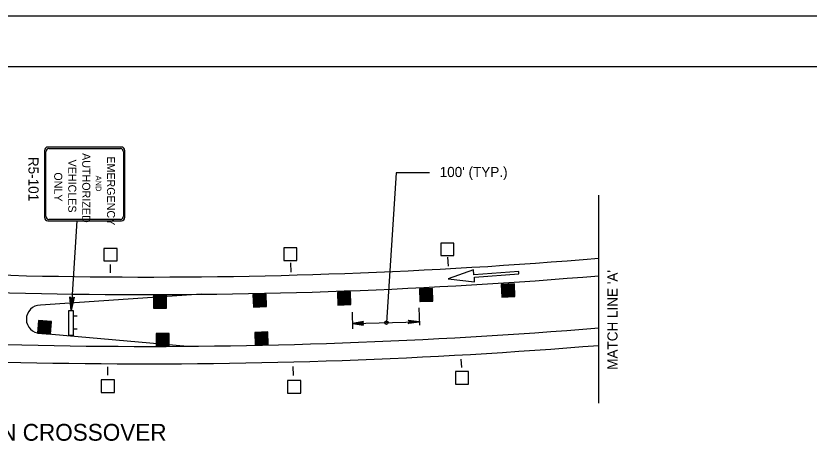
# Model space of a CAD drawing. Extents: x 640253 to 641999, y 298458 to 299646.
# Drawn here: x 641285.7 to 641521.2, y 299517.6 to 299645.6 of the extents above; entities that cross this region are included whole.
import ezdxf

# ---------------------------------------------------------------- set-up
doc = ezdxf.new("R2010")
doc.units = 0
for name, color, linetype in [('1', 7, 'Continuous'), ('2', 7, 'Continuous'), ('PLT-BNDY', 7, 'Continuous')]:
    doc.layers.add(name, color=color, linetype=linetype)

msp = doc.modelspace()

# ---------------------------------------------------------------- linework, layer by layer
at = {"layer": '1'}
msp.add_line((641134.31, 299630.63), (641920.31, 299630.63), dxfattribs=at)
at = {"layer": '2'}
for p, q in [((641317.01, 299606.68), (641295.14, 299606.68)), ((641295.42, 299606.27), (641316.73, 299606.27)), ((641294.19, 299605.58), (641294.19, 299585.83)), ((641294.54, 299586.15), (641294.54, 299605.26)), ((641317.61, 299605.26), (641317.61, 299586.15)), ((641317.96, 299585.83), (641317.96, 299605.58)), ((641458.78, 299530.67), (641458.78, 299592.35)), ((641295.14, 299584.73), (641317.01, 299584.73)), ((641316.73, 299585.14), (641295.42, 299585.14)), ((641414.07, 299571.28), (641413.91, 299574.01)), ((641313.76, 299569.29), (641313.78, 299571.77)), ((641367.39, 299569.57), (641367.33, 299572.3)), ((641421.56, 299570.22), (641414, 299567.58)), ((641421.66, 299568.78), (641421.56, 299570.22)), ((641434.95, 299569.7), (641421.66, 299568.78)), ((641421.79, 299568.08), (641435, 299568.99)), ((641421.88, 299566.64), (641421.79, 299568.08)), ((641435, 299568.99), (641434.95, 299569.7)), ((641414, 299567.58), (641421.88, 299566.64)), ((641292.94, 299559.81), (641337.84, 299562.94)), ((641339.24, 299562.96), (641340.74, 299563.06)), ((641405.33, 299558.94), (641405.46, 299553.77)), ((641302.59, 299556.51), (641303.84, 299556.51)), ((641385.52, 299557.67), (641385.64, 299552.69)), ((641385.6, 299554.3), (641405.43, 299554.77)), ((641302.59, 299552.66), (641303.84, 299552.66)), ((641292.94, 299551.4), (641336.58, 299547.52)), ((641418.05, 299541.21), (641417.9, 299543.69)), ((641312.92, 299538.92), (641312.94, 299541.4)), ((641368.05, 299538.84), (641367.99, 299541.56))]:
    msp.add_line(p, q, dxfattribs=at)
for points in [[(641408.49, 299598.98), (641398.57, 299598.98), (641395.68, 299554.54)], [(641303.8, 299584.73), (641302.04, 299558.18)], [(641429.91, 299562.14), (641433.81, 299562.28), (641433.68, 299566.02), (641429.78, 299565.88), (641429.91, 299562.14), (641433.62, 299565.95), (641429.85, 299565.82), (641429.98, 299562.19), (641433.74, 299562.32), (641433.62, 299565.88), (641429.93, 299565.75), (641430.05, 299562.26), (641433.66, 299562.39), (641433.53, 299565.79), (641430, 299565.66), (641430.12, 299562.32), (641433.59, 299562.45), (641433.48, 299565.73), (641430.07, 299565.61), (641430.18, 299562.39), (641433.51, 299562.51), (641433.39, 299565.66), (641430.14, 299565.54), (641430.24, 299562.45), (641433.44, 299562.58), (641433.32, 299565.58), (641430.21, 299565.47), (641430.31, 299562.52), (641433.37, 299562.64), (641433.25, 299565.51), (641430.28, 299565.4), (641430.36, 299562.6), (641433.28, 299562.72), (641433.19, 299565.42), (641430.37, 299565.33), (641430.43, 299562.65), (641433.18, 299562.79), (641433.1, 299565.35), (641430.45, 299565.26), (641430.5, 299562.72), (641433.1, 299562.85), (641433.02, 299565.29), (641430.53, 299565.19), (641430.58, 299562.76), (641433.01, 299562.91), (641432.92, 299565.21), (641430.63, 299565.1), (641430.61, 299564), (641430.65, 299562.83), (641432.93, 299562.99), (641432.83, 299565.11), (641430.71, 299565), (641430.74, 299562.91), (641432.84, 299563.05), (641432.74, 299565.03), (641430.82, 299564.9), (641430.84, 299563), (641432.71, 299563.12), (641432.63, 299564.9), (641430.96, 299564.8), (641430.96, 299563.14), (641432.56, 299563.22), (641432.49, 299564.79), (641431.12, 299564.68), (641431.09, 299563.26), (641431.1, 299563.26), (641432.41, 299563.35), (641432.36, 299564.64), (641431.26, 299564.56), (641431.23, 299563.39), (641432.25, 299563.49), (641432.22, 299564.48), (641431.4, 299564.43), (641431.39, 299563.55), (641432.09, 299563.6), (641432.04, 299564.34), (641431.57, 299564.3), (641431.57, 299563.69), (641431.91, 299563.74), (641431.9, 299564.18), (641431.75, 299564.21), (641431.74, 299563.85)], [(641381.24, 299559.77), (641385.14, 299559.9), (641385.01, 299563.65), (641381.11, 299563.51), (641381.24, 299559.77), (641384.95, 299563.57), (641381.18, 299563.44), (641381.3, 299559.82), (641385.07, 299559.95), (641384.95, 299563.51), (641381.26, 299563.38), (641381.38, 299559.89), (641384.99, 299560.02), (641384.86, 299563.42), (641381.33, 299563.29), (641381.45, 299559.95), (641384.92, 299560.07), (641384.81, 299563.36), (641381.4, 299563.24), (641381.51, 299560.01), (641384.84, 299560.14), (641384.72, 299563.28), (641381.47, 299563.17), (641381.57, 299560.07), (641384.77, 299560.2), (641384.65, 299563.21), (641381.54, 299563.1), (641381.63, 299560.14), (641384.7, 299560.27), (641384.58, 299563.14), (641381.61, 299563.03), (641381.69, 299560.22), (641384.61, 299560.35), (641384.52, 299563.04), (641381.7, 299562.96), (641381.76, 299560.27), (641384.51, 299560.42), (641384.43, 299562.98), (641381.78, 299562.89), (641381.83, 299560.34), (641384.43, 299560.48), (641384.34, 299562.92), (641381.86, 299562.81), (641381.91, 299560.39), (641384.34, 299560.54), (641384.25, 299562.84), (641381.96, 299562.73), (641381.94, 299561.63), (641381.98, 299560.46), (641384.26, 299560.61), (641384.16, 299562.74), (641382.03, 299562.62), (641382.07, 299560.54), (641384.17, 299560.68), (641384.07, 299562.66), (641382.15, 299562.53), (641382.17, 299560.63), (641384.04, 299560.74), (641383.96, 299562.52), (641382.28, 299562.43), (641382.28, 299560.76), (641383.89, 299560.85), (641383.82, 299562.41), (641382.45, 299562.31), (641382.42, 299560.88), (641382.43, 299560.88), (641383.74, 299560.98), (641383.68, 299562.26), (641382.58, 299562.19), (641382.56, 299561.01), (641383.58, 299561.11), (641383.55, 299562.1), (641382.73, 299562.06), (641382.72, 299561.17), (641383.42, 299561.23), (641383.36, 299561.97), (641382.9, 299561.92), (641382.9, 299561.32), (641383.24, 299561.36), (641383.23, 299561.81), (641383.08, 299561.83), (641383.07, 299561.47)], [(641405.61, 299560.8), (641409.51, 299560.94), (641409.38, 299564.69), (641405.48, 299564.55), (641405.61, 299560.8), (641409.32, 299564.61), (641405.55, 299564.48), (641405.68, 299560.86), (641409.45, 299560.99), (641409.32, 299564.55), (641405.63, 299564.42), (641405.75, 299560.93), (641409.36, 299561.05), (641409.24, 299564.45), (641405.7, 299564.33), (641405.82, 299560.99), (641409.29, 299561.11), (641409.18, 299564.39), (641405.77, 299564.27), (641405.88, 299561.05), (641409.22, 299561.17), (641409.09, 299564.32), (641405.84, 299564.21), (641405.94, 299561.11), (641409.14, 299561.24), (641409.02, 299564.25), (641405.91, 299564.14), (641406.01, 299561.18), (641409.07, 299561.31), (641408.96, 299564.17), (641405.98, 299564.07), (641406.06, 299561.26), (641408.98, 299561.38), (641408.89, 299564.08), (641406.07, 299563.99), (641406.13, 299561.31), (641408.88, 299561.46), (641408.8, 299564.02), (641406.15, 299563.93), (641406.2, 299561.38), (641408.8, 299561.51), (641408.72, 299563.96), (641406.23, 299563.85), (641406.28, 299561.42), (641408.71, 299561.58), (641408.62, 299563.88), (641406.33, 299563.77), (641406.31, 299562.67), (641406.36, 299561.5), (641408.63, 299561.65), (641408.53, 299563.78), (641406.41, 299563.66), (641406.44, 299561.58), (641408.54, 299561.72), (641408.44, 299563.7), (641406.51, 299563.57), (641406.55, 299561.67), (641408.41, 299561.78), (641408.33, 299563.56), (641406.66, 299563.47), (641406.66, 299561.8), (641408.26, 299561.88), (641408.19, 299563.45), (641406.82, 299563.35), (641406.79, 299561.92), (641406.8, 299561.92), (641408.11, 299562.02), (641408.06, 299563.3), (641406.96, 299563.22), (641406.93, 299562.05), (641407.95, 299562.15), (641407.93, 299563.14), (641407.1, 299563.09), (641407.09, 299562.21), (641407.79, 299562.27), (641407.74, 299563.01), (641407.27, 299562.96), (641407.27, 299562.36), (641407.61, 299562.4), (641407.59, 299562.85), (641407.45, 299562.87), (641407.44, 299562.51)], [(641302.76, 299561.93), (641302.47, 299561.81), (641302.04, 299558.18), (641302.76, 299561.93), (641302.93, 299562.1), (641302.04, 299558.18), (641302.1, 299561.83), (641301.83, 299561.97), (641302.04, 299558.18), (641301.66, 299562.2), (641301.83, 299561.97)], [(641326.48, 299558.84), (641330.38, 299558.84), (641330.38, 299562.59), (641326.48, 299562.59), (641326.48, 299558.84), (641330.32, 299562.52), (641326.55, 299562.52), (641326.55, 299558.89), (641330.32, 299558.89), (641330.32, 299562.45), (641326.62, 299562.45), (641326.62, 299558.96), (641330.24, 299558.96), (641330.23, 299562.36), (641326.69, 299562.36), (641326.69, 299559.02), (641330.17, 299559.02), (641330.17, 299562.3), (641326.76, 299562.3), (641326.76, 299559.08), (641330.09, 299559.09), (641330.08, 299562.24), (641326.83, 299562.24), (641326.82, 299559.14), (641330.03, 299559.16), (641330.01, 299562.16), (641326.9, 299562.16), (641326.89, 299559.2), (641329.96, 299559.22), (641329.94, 299562.09), (641326.96, 299562.09), (641326.95, 299559.28), (641329.87, 299559.3), (641329.87, 299562), (641327.05, 299562.01), (641327.01, 299559.33), (641329.77, 299559.38), (641329.78, 299561.94), (641327.13, 299561.94), (641327.09, 299559.4), (641329.69, 299559.44), (641329.69, 299561.89), (641327.21, 299561.87), (641327.17, 299559.44), (641329.6, 299559.51), (641329.6, 299561.81), (641327.3, 299561.78), (641327.25, 299560.68), (641327.25, 299559.51), (641329.53, 299559.59), (641329.5, 299561.71), (641327.37, 299561.67), (641327.33, 299559.59), (641329.44, 299559.65), (641329.41, 299561.63), (641327.48, 299561.57), (641327.44, 299559.67), (641329.31, 299559.72), (641329.3, 299561.5), (641327.62, 299561.47), (641327.56, 299559.8), (641329.17, 299559.83), (641329.15, 299561.4), (641327.77, 299561.34), (641327.7, 299559.91), (641327.71, 299559.91), (641329.02, 299559.97), (641329.01, 299561.25), (641327.91, 299561.21), (641327.84, 299560.05), (641328.86, 299560.1), (641328.87, 299561.1), (641328.05, 299561.08), (641328.01, 299560.2), (641328.71, 299560.23), (641328.68, 299560.97), (641328.21, 299560.94), (641328.19, 299560.34), (641328.53, 299560.37), (641328.53, 299560.81), (641328.39, 299560.84), (641328.37, 299560.48)], [(641356.19, 299559.16), (641360.08, 299559.3), (641359.96, 299563.04), (641356.06, 299562.9), (641356.19, 299559.16), (641359.9, 299562.97), (641356.13, 299562.84), (641356.25, 299559.21), (641360.02, 299559.34), (641359.9, 299562.9), (641356.21, 299562.77), (641356.33, 299559.28), (641359.94, 299559.41), (641359.81, 299562.81), (641356.28, 299562.68), (641356.39, 299559.34), (641359.87, 299559.47), (641359.76, 299562.75), (641356.35, 299562.63), (641356.46, 299559.41), (641359.79, 299559.53), (641359.67, 299562.68), (641356.42, 299562.56), (641356.52, 299559.47), (641359.72, 299559.6), (641359.59, 299562.6), (641356.49, 299562.49), (641356.58, 299559.54), (641359.65, 299559.66), (641359.53, 299562.53), (641356.56, 299562.42), (641356.64, 299559.62), (641359.56, 299559.74), (641359.47, 299562.44), (641356.65, 299562.35), (641356.71, 299559.67), (641359.46, 299559.81), (641359.38, 299562.37), (641356.73, 299562.28), (641356.78, 299559.74), (641359.38, 299559.87), (641359.29, 299562.31), (641356.81, 299562.21), (641356.86, 299559.78), (641359.29, 299559.93), (641359.2, 299562.23), (641356.9, 299562.12), (641356.89, 299561.02), (641356.93, 299559.85), (641359.21, 299560.01), (641359.11, 299562.13), (641356.98, 299562.02), (641357.02, 299559.93), (641359.12, 299560.07), (641359.02, 299562.05), (641357.09, 299561.92), (641357.12, 299560.02), (641358.99, 299560.14), (641358.91, 299561.92), (641357.23, 299561.82), (641357.23, 299560.15), (641358.84, 299560.24), (641358.77, 299561.81), (641357.39, 299561.7), (641357.37, 299560.27), (641357.38, 299560.27), (641358.69, 299560.37), (641358.63, 299561.66), (641357.53, 299561.58), (641357.51, 299560.41), (641358.53, 299560.5), (641358.5, 299561.49), (641357.68, 299561.45), (641357.67, 299560.57), (641358.37, 299560.62), (641358.31, 299561.36), (641357.85, 299561.32), (641357.85, 299560.71), (641358.19, 299560.75), (641358.17, 299561.2), (641358.03, 299561.22), (641358.02, 299560.86)], [(641292.09, 299551.42), (641295.98, 299551.15), (641296.24, 299554.89), (641292.35, 299555.16), (641292.09, 299551.42), (641296.17, 299554.82), (641292.41, 299555.09), (641292.16, 299551.47), (641295.92, 299551.21), (641296.16, 299554.76), (641292.48, 299555.01), (641292.24, 299551.53), (641295.84, 299551.28), (641296.07, 299554.67), (641292.54, 299554.92), (641292.31, 299551.59), (641295.78, 299551.35), (641296.01, 299554.62), (641292.61, 299554.86), (641292.38, 299551.64), (641295.71, 299551.42), (641295.92, 299554.56), (641292.67, 299554.79), (641292.45, 299551.7), (641295.64, 299551.49), (641295.83, 299554.49), (641292.73, 299554.71), (641292.52, 299551.76), (641295.58, 299551.56), (641295.76, 299554.42), (641292.8, 299554.63), (641292.58, 299551.83), (641295.5, 299551.65), (641295.69, 299554.34), (641292.88, 299554.55), (641292.65, 299551.87), (641295.41, 299551.73), (641295.59, 299554.29), (641292.95, 299554.47), (641292.73, 299551.94), (641295.33, 299551.79), (641295.5, 299554.24), (641293.02, 299554.39), (641292.82, 299551.97), (641295.25, 299551.87), (641295.4, 299554.16), (641293.11, 299554.29), (641292.98, 299553.2), (641292.9, 299552.03), (641295.18, 299551.95), (641295.3, 299554.07), (641293.17, 299554.19), (641292.99, 299552.11), (641295.09, 299552.02), (641295.2, 299554), (641293.27, 299554.08), (641293.1, 299552.19), (641294.97, 299552.1), (641295.08, 299553.89), (641293.4, 299553.96), (641293.23, 299552.3), (641294.83, 299552.22), (641294.92, 299553.79), (641293.55, 299553.82), (641293.37, 299552.41), (641293.38, 299552.41), (641294.7, 299552.37), (641294.78, 299553.65), (641293.68, 299553.69), (641293.53, 299552.53), (641294.55, 299552.51), (641294.63, 299553.51), (641293.81, 299553.55), (641293.7, 299552.67), (641294.4, 299552.65), (641294.43, 299553.39), (641293.96, 299553.4), (641293.9, 299552.79), (641294.24, 299552.8), (641294.27, 299553.25), (641294.13, 299553.29), (641294.08, 299552.93)], [(641388.76, 299554.7), (641388.64, 299554.47), (641385.6, 299554.3), (641388.76, 299554.7), (641388.91, 299554.84), (641385.6, 299554.3), (641388.64, 299554.14), (641388.74, 299553.92), (641385.6, 299554.3), (641388.91, 299553.78), (641388.74, 299553.92)], [(641402.27, 299555.17), (641402.4, 299554.94), (641405.43, 299554.77), (641402.27, 299555.17), (641402.12, 299555.31), (641405.43, 299554.77), (641402.4, 299554.61), (641402.29, 299554.39), (641405.43, 299554.77), (641402.12, 299554.25), (641402.29, 299554.39)], [(641356.71, 299547.91), (641360.61, 299548.05), (641360.48, 299551.79), (641356.58, 299551.65), (641356.71, 299547.91), (641360.42, 299551.72), (641356.65, 299551.59), (641356.78, 299547.96), (641360.55, 299548.1), (641360.42, 299551.65), (641356.73, 299551.52), (641356.85, 299548.04), (641360.46, 299548.16), (641360.34, 299551.56), (641356.8, 299551.44), (641356.92, 299548.1), (641360.39, 299548.21), (641360.28, 299551.5), (641356.87, 299551.38), (641356.98, 299548.16), (641360.32, 299548.28), (641360.19, 299551.43), (641356.94, 299551.31), (641357.04, 299548.21), (641360.24, 299548.35), (641360.12, 299551.35), (641357.01, 299551.24), (641357.11, 299548.29), (641360.17, 299548.41), (641360.06, 299551.28), (641357.08, 299551.17), (641357.16, 299548.37), (641360.08, 299548.49), (641359.99, 299551.19), (641357.17, 299551.1), (641357.23, 299548.42), (641359.98, 299548.56), (641359.9, 299551.12), (641357.25, 299551.03), (641357.3, 299548.49), (641359.9, 299548.62), (641359.82, 299551.06), (641357.33, 299550.96), (641357.38, 299548.53), (641359.81, 299548.68), (641359.72, 299550.98), (641357.43, 299550.87), (641357.41, 299549.77), (641357.46, 299548.6), (641359.73, 299548.76), (641359.63, 299550.88), (641357.51, 299550.77), (641357.54, 299548.68), (641359.64, 299548.82), (641359.55, 299550.8), (641357.62, 299550.67), (641357.65, 299548.77), (641359.51, 299548.89), (641359.43, 299550.67), (641357.76, 299550.57), (641357.76, 299548.9), (641359.36, 299548.99), (641359.29, 299550.56), (641357.92, 299550.45), (641357.89, 299549.02), (641357.9, 299549.02), (641359.21, 299549.12), (641359.16, 299550.41), (641358.06, 299550.33), (641358.03, 299549.16), (641359.05, 299549.25), (641359.03, 299550.25), (641358.2, 299550.2), (641358.19, 299549.32), (641358.89, 299549.37), (641358.84, 299550.11), (641358.37, 299550.07), (641358.37, 299549.46), (641358.71, 299549.5), (641358.7, 299549.95), (641358.55, 299549.97), (641358.54, 299549.61)], [(641327.29, 299547.54), (641331.19, 299547.54), (641331.19, 299551.29), (641327.29, 299551.29), (641327.29, 299547.54), (641331.13, 299551.21), (641327.36, 299551.21), (641327.36, 299547.59), (641331.13, 299547.59), (641331.13, 299551.15), (641327.43, 299551.15), (641327.43, 299547.66), (641331.05, 299547.66), (641331.04, 299551.06), (641327.5, 299551.06), (641327.5, 299547.72), (641330.98, 299547.72), (641330.98, 299551), (641327.57, 299551), (641327.57, 299547.77), (641330.91, 299547.79), (641330.9, 299550.93), (641327.64, 299550.93), (641327.63, 299547.84), (641330.84, 299547.85), (641330.82, 299550.86), (641327.71, 299550.86), (641327.7, 299547.9), (641330.77, 299547.92), (641330.75, 299550.79), (641327.78, 299550.79), (641327.76, 299547.98), (641330.68, 299548), (641330.68, 299550.7), (641327.86, 299550.71), (641327.82, 299548.03), (641330.58, 299548.08), (641330.59, 299550.64), (641327.94, 299550.64), (641327.9, 299548.1), (641330.51, 299548.14), (641330.51, 299550.58), (641328.02, 299550.56), (641327.98, 299548.14), (641330.42, 299548.2), (641330.41, 299550.51), (641328.11, 299550.47), (641328.06, 299549.37), (641328.06, 299548.2), (641330.34, 299548.28), (641330.31, 299550.41), (641328.19, 299550.37), (641328.15, 299548.28), (641330.25, 299548.35), (641330.22, 299550.33), (641328.29, 299550.27), (641328.26, 299548.37), (641330.12, 299548.42), (641330.11, 299550.2), (641328.43, 299550.16), (641328.37, 299548.5), (641329.98, 299548.52), (641329.96, 299550.1), (641328.58, 299550.04), (641328.51, 299548.61), (641328.52, 299548.61), (641329.83, 299548.66), (641329.82, 299549.95), (641328.72, 299549.91), (641328.65, 299548.74), (641329.68, 299548.8), (641329.68, 299549.79), (641328.86, 299549.77), (641328.82, 299548.9), (641329.52, 299548.92), (641329.49, 299549.67), (641329.03, 299549.64), (641329.01, 299549.03), (641329.34, 299549.06), (641329.34, 299549.51), (641329.2, 299549.54), (641329.18, 299549.18)]]:
    msp.add_lwpolyline(points, dxfattribs=at)
for points in [[(641411.83, 299574.43), (641415.72, 299574.43), (641415.72, 299578.17), (641411.83, 299578.17)], [(641311.81, 299572.84), (641315.7, 299572.84), (641315.7, 299576.58), (641311.81, 299576.58)], [(641365.22, 299572.95), (641369.11, 299572.95), (641369.11, 299576.7), (641365.22, 299576.7)], [(641301.37, 299550.68), (641301.37, 299558.18), (641302.62, 299558.18), (641302.62, 299550.68)], [(641416.2, 299536.29), (641420.1, 299536.29), (641420.1, 299540.04), (641416.2, 299540.04)], [(641311.01, 299533.83), (641314.9, 299533.83), (641314.9, 299537.58), (641311.01, 299537.58)], [(641366.34, 299533.63), (641370.24, 299533.63), (641370.24, 299537.37), (641366.34, 299537.37)]]:
    msp.add_lwpolyline(points, close=True, dxfattribs=at)
msp.add_circle((641395.68, 299554.54), 0.515, dxfattribs=at)
for centre, radius, start, end in [((641324.62, 301181.29), 1613.21, 264.03084, 274.7698), ((641324.62, 301181.29), 1618.4, 264.02808, 274.75447), ((641292.94, 299555.56), 4.17, 90, 270), ((641324.62, 301181.29), 1633.8, 264.01999, 274.70955), ((641324.62, 301181.29), 1638.99, 264.0173, 274.6946)]:
    msp.add_arc(centre, radius, start, end, dxfattribs=at)
for centre, major_axis, start_param, end_param in [((641295.14, 299605.58), (0, -1.1), 3.141593, 4.712389), ((641295.42, 299605.25), (0, -1.01), 3.141593, 4.712389), ((641316.73, 299605.25), (0, 1.01), 4.712389, 6.283185), ((641317.01, 299605.58), (0, 1.1), 4.712389, 6.283185), ((641295.14, 299585.83), (0, -1.1), 4.712389, 6.283185), ((641295.42, 299586.15), (0, -1.01), 4.712389, 6.283185), ((641316.73, 299586.15), (0, 1.01), 3.141593, 4.712389), ((641317.01, 299585.83), (0, 1.1), 3.141593, 4.712389)]:
    msp.add_ellipse(centre, major_axis=major_axis, ratio=0.866667, start_param=start_param, end_param=end_param, dxfattribs=at)
at = {"layer": 'PLT-BNDY'}
msp.add_lwpolyline([(641094.31, 299645.63), (641935.31, 299645.63), (641935.31, 299051.63), (641094.31, 299051.63)], close=True, dxfattribs=at)

# ---------------------------------------------------------------- texts
at = {"layer": '2'}
for s, height, rotation, p in [('R5-101', 3, 270, (641289.39, 299603.76)), ('AUTHORIZED', 2.377, 270, (641305.36, 299604.87)), ('EMERGENCY', 2.377, 270, (641312.71, 299603.92)), ('VEHICLES', 2.377, 270, (641301.2, 299602.95)), ('ONLY', 2.377, 270, (641297.04, 299599.16)), ('AND', 1.664, 270, (641309.39, 299598.2)), ("MATCH LINE 'A'", 3, 90, (641464.3, 299540.54))]:
    msp.add_text(s, height=height, rotation=rotation, dxfattribs=at).set_placement(p)
for s, height, p in [("100' (TYP.)", 3, (641411.49, 299597.77)), ('MEDIAN CROSSOVER', 5, (641259.81, 299519.47))]:
    msp.add_text(s, height=height, dxfattribs=at).set_placement(p)

doc.saveas('drawing.dxf')
